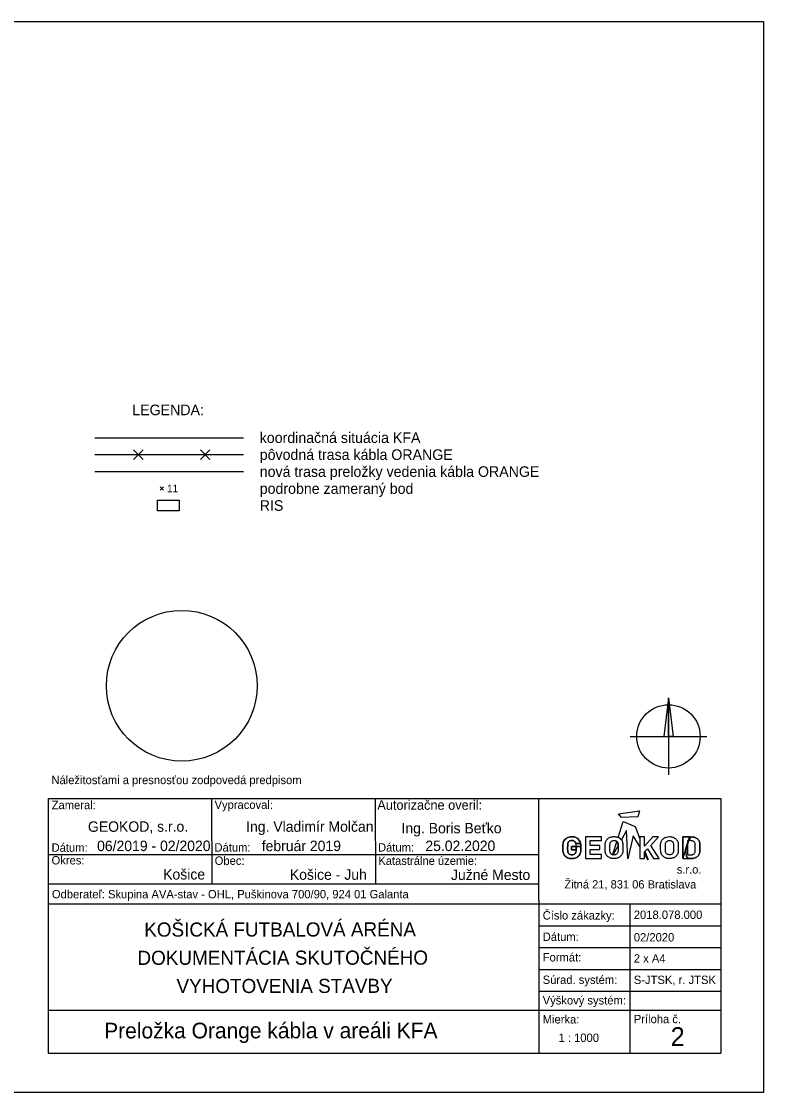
# Model space of a CAD drawing. Extents: x -264095 to -263675, y -1242370 to -1242073.
# Drawn here: x -263880.9 to -263675.1, y -1242369.5 to -1242072.5 of the extents above; entities that cross this region are included whole.
import ezdxf

# ---------------------------------------------------------------- set-up
doc = ezdxf.new("R2010")
doc.units = 0
for name, color, linetype in [('LEGENDA', 7, 'Continuous'), ('RAM_NA_TLAC_A3_1-1000', 7, 'Continuous'), ('ROZPISKA', 7, 'Continuous')]:
    doc.layers.add(name, color=color, linetype=linetype)

msp = doc.modelspace()

# ---------------------------------------------------------------- linework, layer by layer
at = {"layer": 'LEGENDA'}
for p, q in [((-263860.59, -1242187.94), (-263819.33, -1242187.94)), ((-263860.59, -1242192.64), (-263819.33, -1242192.64)), ((-263849.8, -1242193.97), (-263847.15, -1242191.32)), ((-263847.15, -1242193.97), (-263849.8, -1242191.32)), ((-263831.29, -1242193.97), (-263828.64, -1242191.32)), ((-263828.64, -1242193.97), (-263831.29, -1242191.32)), ((-263860.59, -1242197.34), (-263819.33, -1242197.34)), ((-263842.47, -1242202.51), (-263841.55, -1242201.58)), ((-263841.55, -1242202.51), (-263842.47, -1242201.58))]:
    msp.add_line(p, q, dxfattribs=at)
msp.add_lwpolyline([(-263843.16, -1242205.25), (-263837.16, -1242205.25), (-263837.16, -1242208.25), (-263843.16, -1242208.25)], close=True, dxfattribs=at)
at = {"layer": 'RAM_NA_TLAC_A3_1-1000'}
msp.add_line((-263675.11, -1242072.53), (-263675.11, -1242082.53), dxfattribs=at)
msp.add_lwpolyline([(-264095.11, -1242072.53), (-263675.11, -1242072.53), (-263675.11, -1242369.53), (-264095.11, -1242369.53)], close=True, dxfattribs=at)
at = {"layer": 'ROZPISKA'}
for p, q in [((-263701.48, -1242260.1), (-263702.74, -1242270.76)), ((-263701.48, -1242260.1), (-263701.48, -1242281.42)), ((-263701.48, -1242260.1), (-263700.22, -1242270.76)), ((-263712.14, -1242270.76), (-263690.82, -1242270.76)), ((-263873.52, -1242287.98), (-263686.99, -1242287.98)), ((-263873.52, -1242287.98), (-263873.52, -1242358.57)), ((-263828.16, -1242287.98), (-263828.14, -1242311.69)), ((-263782.78, -1242287.99), (-263782.77, -1242311.68)), ((-263737.4, -1242316.21), (-263737.4, -1242287.98)), ((-263686.99, -1242287.98), (-263686.98, -1242358.57)), ((-263715.48, -1242298.76), (-263714.02, -1242294.33)), ((-263714.02, -1242294.33), (-263710.76, -1242295.71)), ((-263713.08, -1242296.85), (-263714.54, -1242299.46)), ((-263712.8, -1242304.75), (-263713.08, -1242296.85)), ((-263710.76, -1242295.71), (-263709.39, -1242299.2)), ((-263725.8, -1242300.47), (-263727.13, -1242300.47)), ((-263727.13, -1242300.47), (-263725.8, -1242300.47)), ((-263715.84, -1242299.86), (-263717.05, -1242303.54)), ((-263716.67, -1242298.55), (-263716.56, -1242298.54)), ((-263716.64, -1242299.61), (-263716.57, -1242299.61)), ((-263716.64, -1242299.61), (-263716.57, -1242299.61)), ((-263711.24, -1242298.35), (-263712.8, -1242304.75)), ((-263709.39, -1242301.32), (-263711.24, -1242298.35)), ((-263708.12, -1242298.62), (-263709.39, -1242298.62)), ((-263709.39, -1242299.2), (-263709.39, -1242301.32)), ((-263705.81, -1242298.62), (-263708.12, -1242301.23)), ((-263708.12, -1242301.23), (-263708.12, -1242298.62)), ((-263706.42, -1242301.03), (-263704.23, -1242298.62)), ((-263704.23, -1242298.62), (-263705.81, -1242298.62)), ((-263697.52, -1242298.64), (-263695.61, -1242298.64)), ((-263697.52, -1242304.6), (-263697.52, -1242298.64)), ((-263697.52, -1242298.64), (-263697.52, -1242304.6)), ((-263695.61, -1242298.64), (-263697.52, -1242298.64)), ((-263696.21, -1242299.68), (-263696.21, -1242303.56)), ((-263696.21, -1242299.68), (-263696.21, -1242303.56)), ((-263873.53, -1242303.47), (-263737.4, -1242303.47)), ((-263707.12, -1242304.98), (-263708.12, -1242303.37)), ((-263708.01, -1242302.7), (-263707.12, -1242304.98)), ((-263704.11, -1242304.6), (-263706.42, -1242301.03)), ((-263705.61, -1242304.6), (-263704.11, -1242304.6)), ((-263873.52, -1242311.68), (-263737.4, -1242311.67)), ((-263873.54, -1242317.23), (-263737.39, -1242317.22)), ((-263737.4, -1242316.21), (-263737.4, -1242334.37)), ((-263737.39, -1242317.22), (-263686.98, -1242317.22)), ((-263712.19, -1242317.23), (-263712.19, -1242335.38)), ((-263737.4, -1242323.27), (-263686.99, -1242323.28)), ((-263737.41, -1242329.32), (-263686.98, -1242329.32)), ((-263737.41, -1242335.37), (-263686.98, -1242335.38)), ((-263737.4, -1242334.37), (-263737.4, -1242358.56)), ((-263712.19, -1242335.38), (-263712.18, -1242358.56)), ((-263737.4, -1242341.43), (-263686.98, -1242341.42)), ((-263873.53, -1242346.67), (-263686.98, -1242346.66)), ((-263873.52, -1242358.57), (-263686.98, -1242358.57))]:
    msp.add_line(p, q, dxfattribs=at)
for points in [[(-263701.48, -1242260.1), (-263700.22, -1242270.76), (-263701.48, -1242270.76)], [(-263715.31, -1242292.27), (-263709.53, -1242291.44), (-263709.94, -1242293.09), (-263714.54, -1242293.24)], [(-263724.49, -1242298.6), (-263724.49, -1242304.6), (-263720.1, -1242304.6), (-263720.1, -1242303.54), (-263723.17, -1242303.54), (-263723.17, -1242302.1), (-263720.54, -1242302.1), (-263720.54, -1242301.06), (-263723.17, -1242301.06), (-263723.17, -1242299.66), (-263720.1, -1242299.66), (-263720.1, -1242298.6)]]:
    msp.add_lwpolyline(points, close=True, dxfattribs=at)
for points in [[(-263715.44, -1242301.08), (-263715.45, -1242300.94), (-263715.45, -1242300.78), (-263715.46, -1242300.63), (-263715.49, -1242300.48), (-263715.52, -1242300.35), (-263715.58, -1242300.2), (-263715.66, -1242300.06), (-263715.74, -1242299.95), (-263715.84, -1242299.86)], [(-263714.54, -1242299.46), (-263714.58, -1242299.4), (-263714.66, -1242299.32), (-263714.74, -1242299.24), (-263714.82, -1242299.17), (-263714.91, -1242299.1), (-263715.01, -1242299.02), (-263715.09, -1242298.97), (-263715.18, -1242298.91), (-263715.29, -1242298.85), (-263715.38, -1242298.8), (-263715.48, -1242298.76)], [(-263709.39, -1242298.62), (-263709.39, -1242304.6), (-263708.12, -1242304.6), (-263708.12, -1242302.81), (-263707.27, -1242301.92), (-263705.61, -1242304.6)], [(-263727.08, -1242302.24), (-263728.34, -1242302.24), (-263728.34, -1242301.25), (-263725.79, -1242301.25)], [(-263725.79, -1242301.25), (-263728.34, -1242301.25), (-263728.34, -1242302.24), (-263727.08, -1242302.24)], [(-263716.85, -1242303.59), (-263715.44, -1242301.08)], [(-263708.12, -1242303.37), (-263708.12, -1242302.81), (-263708.01, -1242302.7)], [(-263717.05, -1242303.54), (-263717.02, -1242303.55), (-263716.98, -1242303.56), (-263716.95, -1242303.57), (-263716.91, -1242303.58), (-263716.87, -1242303.59), (-263716.85, -1242303.59)]]:
    msp.add_lwpolyline(points, dxfattribs=at)
for centre, radius in [((-263836.46, -1242256.74), 20.9), ((-263701.48, -1242270.76), 8.78)]:
    msp.add_circle(centre, radius, dxfattribs=at)
for points in [[(-263725.79, -1242301.25), (-263725.79, -1242302.01), (-263725.8, -1242302.69), (-263725.94, -1242303.29), (-263726.23, -1242303.78), (-263726.68, -1242304.19), (-263727.15, -1242304.46), (-263727.77, -1242304.61), (-263728.33, -1242304.65), (-263728.91, -1242304.61), (-263729.5, -1242304.42), (-263730, -1242304.09), (-263730.39, -1242303.7), (-263730.64, -1242303.17), (-263730.76, -1242302.59), (-263730.78, -1242302.2), (-263730.78, -1242301.02), (-263730.74, -1242300.38), (-263730.57, -1242299.83), (-263730.27, -1242299.37), (-263729.69, -1242298.9), (-263729.07, -1242298.63), (-263728.35, -1242298.55), (-263727.59, -1242298.61), (-263726.8, -1242298.94), (-263726.17, -1242299.52), (-263725.8, -1242300.47), (-263725.79, -1242301.25), (-263725.8, -1242300.47)], [(-263725.8, -1242300.47), (-263726.17, -1242299.52), (-263726.8, -1242298.94), (-263727.59, -1242298.61), (-263728.35, -1242298.55), (-263729.07, -1242298.63), (-263729.69, -1242298.9), (-263730.27, -1242299.37), (-263730.57, -1242299.83), (-263730.74, -1242300.38), (-263730.78, -1242301.02), (-263730.78, -1242302.2), (-263730.76, -1242302.59), (-263730.64, -1242303.17), (-263730.39, -1242303.7), (-263730, -1242304.09), (-263729.5, -1242304.42), (-263728.91, -1242304.61), (-263728.33, -1242304.65), (-263727.77, -1242304.61), (-263727.15, -1242304.46), (-263726.68, -1242304.19), (-263726.23, -1242303.78), (-263725.94, -1242303.29), (-263725.8, -1242302.69), (-263725.79, -1242302.01), (-263725.79, -1242301.25), (-263725.8, -1242300.47), (-263725.79, -1242301.25)], [(-263727.12, -1242300.47), (-263727.25, -1242300.15), (-263727.54, -1242299.83), (-263727.94, -1242299.64), (-263728.33, -1242299.61), (-263728.73, -1242299.66), (-263729.05, -1242299.84), (-263729.29, -1242300.1), (-263729.4, -1242300.37), (-263729.41, -1242300.78), (-263729.44, -1242301.22), (-263729.45, -1242301.76), (-263729.44, -1242302.39), (-263729.39, -1242302.86), (-263729.22, -1242303.23), (-263728.97, -1242303.44), (-263728.66, -1242303.57), (-263728.34, -1242303.6), (-263727.97, -1242303.59), (-263727.57, -1242303.42), (-263727.29, -1242303.15), (-263727.12, -1242302.84), (-263727.08, -1242302.48), (-263727.08, -1242302.24), (-263727.12, -1242300.47), (-263727.08, -1242302.24)], [(-263727.08, -1242302.24), (-263727.08, -1242302.48), (-263727.12, -1242302.84), (-263727.29, -1242303.15), (-263727.57, -1242303.42), (-263727.97, -1242303.59), (-263728.34, -1242303.6), (-263728.66, -1242303.57), (-263728.97, -1242303.44), (-263729.22, -1242303.23), (-263729.39, -1242302.86), (-263729.44, -1242302.39), (-263729.45, -1242301.76), (-263729.44, -1242301.22), (-263729.41, -1242300.78), (-263729.4, -1242300.37), (-263729.29, -1242300.1), (-263729.05, -1242299.84), (-263728.73, -1242299.66), (-263728.33, -1242299.61), (-263727.94, -1242299.64), (-263727.54, -1242299.83), (-263727.25, -1242300.15), (-263727.12, -1242300.47), (-263727.08, -1242302.24), (-263727.12, -1242300.47)], [(-263716.56, -1242298.54), (-263716.53, -1242298.54), (-263716.35, -1242298.54), (-263716.02, -1242298.62), (-263715.56, -1242298.7), (-263715.14, -1242298.93), (-263714.75, -1242299.2), (-263714.43, -1242299.57), (-263714.25, -1242299.99), (-263714.14, -1242300.45), (-263714.14, -1242301.17), (-263714.12, -1242301.92), (-263714.13, -1242302.65), (-263714.2, -1242303.11), (-263714.37, -1242303.5), (-263714.59, -1242303.84), (-263714.9, -1242304.1), (-263715.22, -1242304.34), (-263715.62, -1242304.5), (-263716.06, -1242304.63), (-263716.54, -1242304.66), (-263716.98, -1242304.63), (-263717.38, -1242304.59), (-263717.72, -1242304.44), (-263718.05, -1242304.25), (-263718.36, -1242304.05), (-263718.64, -1242303.76), (-263718.86, -1242303.37), (-263719.02, -1242302.9), (-263719.08, -1242302.12), (-263719.02, -1242301.39), (-263719.06, -1242300.69), (-263718.99, -1242300.29), (-263718.9, -1242299.9), (-263718.71, -1242299.55), (-263718.46, -1242299.27), (-263718.19, -1242299.01), (-263717.85, -1242298.83), (-263717.46, -1242298.66), (-263717.05, -1242298.57), (-263716.78, -1242298.55), (-263716.67, -1242298.55)], [(-263716.57, -1242299.61), (-263716.52, -1242299.61), (-263716.38, -1242299.62), (-263716.14, -1242299.67), (-263715.88, -1242299.81), (-263715.64, -1242300.03), (-263715.49, -1242300.37), (-263715.44, -1242300.74), (-263715.45, -1242301.14), (-263715.43, -1242301.57), (-263715.45, -1242302.01), (-263715.43, -1242302.41), (-263715.49, -1242302.76), (-263715.57, -1242303.06), (-263715.76, -1242303.34), (-263716.04, -1242303.52), (-263716.35, -1242303.61), (-263716.6, -1242303.59), (-263716.82, -1242303.61), (-263717.07, -1242303.55), (-263717.3, -1242303.4), (-263717.53, -1242303.18), (-263717.69, -1242302.86), (-263717.74, -1242302.47), (-263717.72, -1242301.99), (-263717.73, -1242301.47), (-263717.72, -1242300.96), (-263717.71, -1242300.55), (-263717.64, -1242300.22), (-263717.46, -1242299.96), (-263717.22, -1242299.76), (-263716.93, -1242299.63), (-263716.73, -1242299.62), (-263716.64, -1242299.61)], [(-263716.57, -1242299.61), (-263716.52, -1242299.61), (-263716.38, -1242299.62), (-263716.14, -1242299.67), (-263715.88, -1242299.81), (-263715.64, -1242300.03), (-263715.49, -1242300.37), (-263715.44, -1242300.74), (-263715.45, -1242301.14), (-263715.43, -1242301.57), (-263715.45, -1242302.01), (-263715.43, -1242302.41), (-263715.49, -1242302.76), (-263715.57, -1242303.06), (-263715.76, -1242303.34), (-263716.04, -1242303.52), (-263716.35, -1242303.61), (-263716.6, -1242303.59), (-263716.82, -1242303.61), (-263717.07, -1242303.55), (-263717.3, -1242303.4), (-263717.53, -1242303.18), (-263717.69, -1242302.86), (-263717.74, -1242302.47), (-263717.72, -1242301.99), (-263717.73, -1242301.47), (-263717.72, -1242300.96), (-263717.71, -1242300.55), (-263717.64, -1242300.22), (-263717.46, -1242299.96), (-263717.22, -1242299.76), (-263716.93, -1242299.63), (-263716.73, -1242299.62), (-263716.64, -1242299.61)], [(-263701.18, -1242298.54), (-263701.62, -1242298.58), (-263702.09, -1242298.68), (-263702.48, -1242298.84), (-263702.8, -1242299.03), (-263703.08, -1242299.27), (-263703.31, -1242299.55), (-263703.51, -1242299.91), (-263703.61, -1242300.3), (-263703.66, -1242300.67), (-263703.66, -1242301.09), (-263703.67, -1242302.39), (-263703.62, -1242302.87), (-263703.45, -1242303.4), (-263703.22, -1242303.78), (-263702.99, -1242304.02), (-263702.65, -1242304.26), (-263702.34, -1242304.43), (-263702.01, -1242304.57), (-263701.61, -1242304.63), (-263701.18, -1242304.65), (-263700.67, -1242304.61), (-263700.22, -1242304.48), (-263699.86, -1242304.33), (-263699.5, -1242304.09), (-263699.23, -1242303.83), (-263699.01, -1242303.51), (-263698.84, -1242303.1), (-263698.77, -1242302.68), (-263698.75, -1242302.16), (-263698.76, -1242300.92), (-263698.78, -1242300.44), (-263698.88, -1242300.01), (-263699.08, -1242299.57), (-263699.36, -1242299.24), (-263699.79, -1242298.92), (-263700.18, -1242298.73), (-263700.64, -1242298.62), (-263701.09, -1242298.54), (-263701.18, -1242298.54), (-263701.18, -1242298.54), (-263701.18, -1242298.54)], [(-263701.2, -1242299.61), (-263701.52, -1242299.64), (-263701.83, -1242299.77), (-263702.08, -1242299.98), (-263702.23, -1242300.21), (-263702.32, -1242300.54), (-263702.34, -1242300.9), (-263702.35, -1242301.44), (-263702.35, -1242302.06), (-263702.35, -1242302.48), (-263702.28, -1242302.86), (-263702.12, -1242303.18), (-263701.91, -1242303.4), (-263701.68, -1242303.53), (-263701.42, -1242303.59), (-263701.22, -1242303.59), (-263701.01, -1242303.59), (-263700.69, -1242303.51), (-263700.37, -1242303.3), (-263700.21, -1242303.06), (-263700.11, -1242302.76), (-263700.06, -1242302.43), (-263700.06, -1242302.04), (-263700.06, -1242301.55), (-263700.06, -1242301.12), (-263700.07, -1242300.77), (-263700.14, -1242300.33), (-263700.28, -1242300.05), (-263700.51, -1242299.82), (-263700.79, -1242299.67), (-263701.02, -1242299.62), (-263701.2, -1242299.61), (-263701.2, -1242299.61), (-263701.2, -1242299.61)], [(-263695.61, -1242298.64), (-263694.99, -1242298.64), (-263694.6, -1242298.66), (-263694.32, -1242298.72), (-263693.95, -1242298.85), (-263693.6, -1242299.05), (-263693.24, -1242299.37), (-263692.98, -1242299.75), (-263692.85, -1242300.11), (-263692.77, -1242300.65), (-263692.76, -1242300.93), (-263692.76, -1242302.11), (-263692.78, -1242302.5), (-263692.8, -1242302.82), (-263692.86, -1242303.16), (-263693.03, -1242303.57), (-263693.33, -1242303.96), (-263693.77, -1242304.31), (-263694.13, -1242304.47), (-263694.49, -1242304.57), (-263694.8, -1242304.6), (-263694.9, -1242304.6), (-263697.52, -1242304.6), (-263695.61, -1242298.64), (-263697.52, -1242304.6)], [(-263697.52, -1242304.6), (-263694.9, -1242304.6), (-263694.8, -1242304.6), (-263694.49, -1242304.57), (-263694.13, -1242304.47), (-263693.77, -1242304.31), (-263693.33, -1242303.96), (-263693.03, -1242303.57), (-263692.86, -1242303.16), (-263692.8, -1242302.82), (-263692.78, -1242302.5), (-263692.76, -1242302.11), (-263692.76, -1242300.93), (-263692.77, -1242300.65), (-263692.85, -1242300.11), (-263692.98, -1242299.75), (-263693.24, -1242299.37), (-263693.6, -1242299.05), (-263693.95, -1242298.85), (-263694.32, -1242298.72), (-263694.6, -1242298.66), (-263694.99, -1242298.64), (-263695.61, -1242298.64), (-263697.52, -1242304.6), (-263695.61, -1242298.64)], [(-263696.21, -1242303.56), (-263695.83, -1242303.57), (-263695.44, -1242303.57), (-263695.02, -1242303.56), (-263694.95, -1242303.57), (-263694.79, -1242303.53), (-263694.55, -1242303.41), (-263694.25, -1242303.2), (-263694.1, -1242302.83), (-263694.06, -1242302.43), (-263694.07, -1242301.87), (-263694.06, -1242301.23), (-263694.07, -1242300.71), (-263694.1, -1242300.36), (-263694.23, -1242300.12), (-263694.5, -1242299.87), (-263694.8, -1242299.73), (-263695.2, -1242299.67), (-263695.48, -1242299.67), (-263696.04, -1242299.68), (-263696.21, -1242299.68)], [(-263696.21, -1242303.56), (-263695.83, -1242303.57), (-263695.44, -1242303.57), (-263695.02, -1242303.56), (-263694.95, -1242303.57), (-263694.79, -1242303.53), (-263694.55, -1242303.41), (-263694.25, -1242303.2), (-263694.1, -1242302.83), (-263694.06, -1242302.43), (-263694.07, -1242301.87), (-263694.06, -1242301.23), (-263694.07, -1242300.71), (-263694.1, -1242300.36), (-263694.23, -1242300.12), (-263694.5, -1242299.87), (-263694.8, -1242299.73), (-263695.2, -1242299.67), (-263695.48, -1242299.67), (-263696.04, -1242299.68), (-263696.21, -1242299.68)]]:
    msp.add_open_spline(points, degree=3, dxfattribs=at)

# ---------------------------------------------------------------- texts
at = {"layer": 'LEGENDA'}
for s, height, p in [('LEGENDA:', 2.939, (-263850.17, -1242181.71)), ('koordinačná situácia KFA', 2.9391, (-263814.83, -1242189.41)), ('pôvodná trasa kábla ORANGE', 2.9391, (-263814.83, -1242194.11)), ('nová trasa preložky vedenia kábla ORANGE', 2.9391, (-263814.83, -1242198.81)), ('11', 2.09, (-263840.54, -1242203.09)), ('podrobne zameraný bod', 2.9391, (-263814.83, -1242203.52)), ('RIS', 2.939, (-263814.83, -1242208.22))]:
    msp.add_text(s, height=height, dxfattribs=at).set_placement(p)
at = {"layer": 'ROZPISKA'}
for s, height, rotation, p in [('Náležitosťami a presnosťou zodpovedá predpisom', 2.3187, 0.0016, (-263872.59, -1242284.01)), ('Zameral:', 2.319, 0.0016, (-263872.52, -1242290.95)), ('Vypracoval:', 2.3187, 0.0016, (-263827.36, -1242290.88)), ('Autorizačne overil:', 2.6427, 0.0016, (-263782.23, -1242291.11)), ('GEOKOD, s.r.o.', 2.8976, 0.0456, (-263862.46, -1242297.23)), ('Ing. Vladimír Molčan', 2.8982, 0.0456, (-263818.6, -1242297.23)), ('Ing. Boris Beťko', 2.8996, 0.0456, (-263775.52, -1242297.66)), ('Dátum:', 2.319, 0.0016, (-263872.55, -1242302.76)), ('06/2019 - 02/2020', 2.8976, 0.0456, (-263859.93, -1242302.58)), ('Dátum:', 2.319, 0.0016, (-263827.38, -1242302.7)), ('február 2019', 2.8976, 0.0456, (-263814.28, -1242302.58)), ('Dátum:', 2.319, 0.0016, (-263782.03, -1242302.7)), ('25.02.2020', 2.898, 0.0456, (-263768.9, -1242302.56)), ('Okres:', 2.319, 0.0016, (-263872.56, -1242306.27)), ('Obec:', 2.319, 0.0016, (-263827.32, -1242306.38)), ('Katastrálne územie:', 2.3187, 0.0016, (-263781.95, -1242306.4)), ('Košice', 2.899, 0.0456, (-263841.61, -1242310.46)), ('Košice - Juh', 2.8996, 0.0456, (-263806.47, -1242310.54)), ('Južné Mesto', 2.8996, 0.0456, (-263761.8, -1242310.6)), ('s.r.o.', 2.299, 0.0016, (-263699.18, -1242308.8)), ('Žitná 21, 831 06 Bratislava', 2.299, 0.0016, (-263730.35, -1242312.94)), ('Odberateľ: Skupina AVA-stav - OHL, Puškinova 700/90, 924 01 Galanta', 2.3181, 0.0016, (-263872.46, -1242315.67)), ('Číslo zákazky:', 2.3181, 0.0016, (-263736.36, -1242321.55)), ('KOŠICKÁ FUTBALOVÁ ARÉNA', 3.9145, 0.0456, (-263846.85, -1242326.29)), ('Dátum:', 2.319, 0.0016, (-263736.36, -1242327.48)), ('DOKUMENTÁCIA SKUTOČNÉHO', 3.9145, 0.0456, (-263848.73, -1242334.12)), ('Formát:', 2.319, 0.0016, (-263736.36, -1242333.18)), ('VYHOTOVENIA STAVBY', 3.9145, 0.0456, (-263837.9, -1242341.94)), ('Súrad. systém:', 2.3181, 0.0016, (-263736.36, -1242339.4)), ('Výškový systém:', 2.3181, 0.0016, (-263736.36, -1242345.1)), ('Mierka:', 2.319, 0.0016, (-263736.36, -1242350.37)), ('Príloha č.', 2.318, 0.0016, (-263711.1, -1242350.29)), ('Preložka Orange kábla v areáli KFA ', 4.3483, 0.0456, (-263857.96, -1242354.52))]:
    msp.add_text(s, height=height, rotation=rotation, dxfattribs=at).set_placement(p)
for s, height, p in [('2018.078.000', 2.322, (-263711.1, -1242321.38)), ('02/2020', 2.322, (-263711.1, -1242327.63)), ('2 x A4', 2.322, (-263711.1, -1242333.49)), ('S-JTSK, r. JTSK', 2.322, (-263711.1, -1242339.42)), ('1 : 1000', 2.322, (-263731.98, -1242355.49)), ('2', 5.22, (-263700.87, -1242356.6))]:
    msp.add_text(s, height=height, dxfattribs=at).set_placement(p)

doc.saveas('drawing.dxf')
